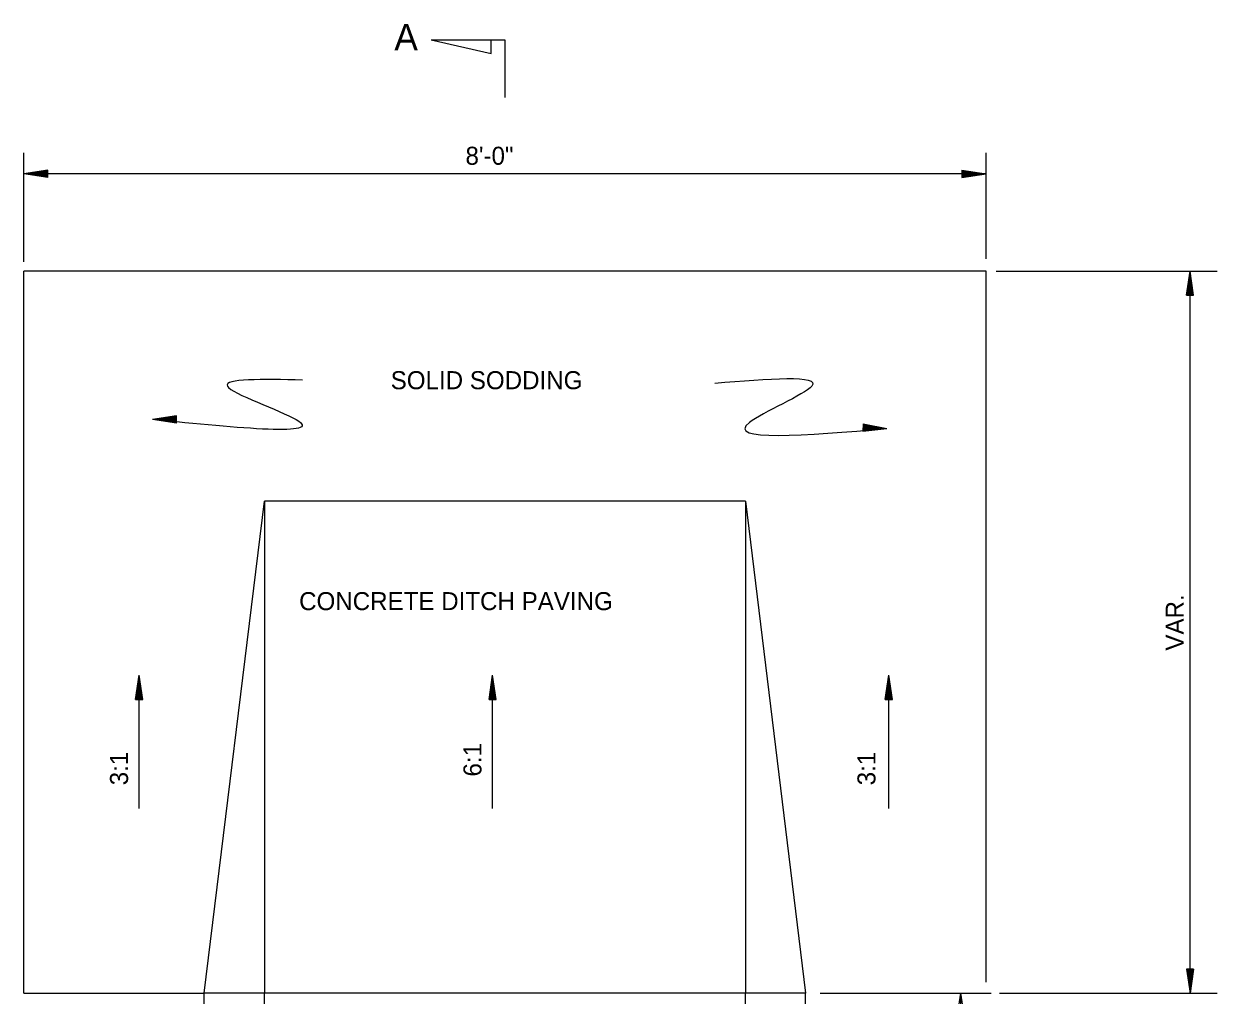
# Model space of a CAD drawing. Extents: x 635488 to 635865, y 290537 to 290973.
# Drawn here: x 635632.8 to 635672.47, y 290826.85 to 290859.13 of the extents above; entities that cross this region are included whole.
import ezdxf

# ---------------------------------------------------------------- set-up
doc = ezdxf.new("R2010")
doc.units = 0
doc.layers.add('Default', color=7, linetype='Continuous')
doc.layers.add('R_Dimension', color=7, linetype='Continuous')

msp = doc.modelspace()

# ---------------------------------------------------------------- linework, layer by layer
at = {"layer": 'Default'}
for p, q in [((635632.798, 290851.226), (635632.798, 290854.85)), ((635664.79, 290851.326), (635664.79, 290854.85)), ((635664.79, 290850.914), (635632.798, 290850.914)), ((635632.798, 290826.914), (635632.798, 290850.914)), ((635664.79, 290827.282), (635664.79, 290850.914)), ((635665.13, 290850.914), (635672.474, 290850.914)), ((635638.798, 290826.914), (635640.794, 290843.274)), ((635656.794, 290843.274), (635640.794, 290843.274)), ((635640.794, 290843.274), (635640.794, 290826.914)), ((635656.794, 290843.274), (635656.794, 290826.914)), ((635656.794, 290843.274), (635658.79, 290826.914)), ((635632.798, 290826.914), (635638.798, 290826.914)), ((635638.798, 290788.918), (635638.798, 290826.914)), ((635658.79, 290826.914), (635638.798, 290826.914)), ((635640.794, 290794.914), (635640.794, 290826.914)), ((635656.79, 290794.914), (635656.79, 290826.914)), ((635658.79, 290788.918), (635658.79, 290826.914)), ((635659.274, 290826.918), (635664.962, 290826.918)), ((635665.234, 290826.918), (635672.474, 290826.918))]:
    msp.add_line(p, q, dxfattribs=at)
at = {"layer": 'R_Dimension'}
for p, q in [((635646.338, 290858.602), (635648.794, 290858.602)), ((635646.338, 290858.602), (635648.338, 290858.15)), ((635648.338, 290858.15), (635648.338, 290858.602)), ((635648.794, 290858.602), (635648.794, 290856.69)), ((635648.794, 290858.602), (635648.794, 290857.15)), ((635633.598, 290854.266), (635632.798, 290854.146)), ((635664.79, 290854.146), (635632.798, 290854.146)), ((635633.598, 290854.026), (635632.798, 290854.146)), ((635633.598, 290854.246), (635632.93, 290854.146)), ((635633.598, 290854.046), (635632.93, 290854.146)), ((635633.598, 290854.226), (635633.07, 290854.146)), ((635633.598, 290854.066), (635633.07, 290854.146)), ((635633.598, 290854.206), (635633.202, 290854.146)), ((635633.598, 290854.086), (635633.202, 290854.146)), ((635633.598, 290854.186), (635633.338, 290854.146)), ((635633.598, 290854.106), (635633.338, 290854.146)), ((635633.598, 290854.166), (635633.47, 290854.146)), ((635633.598, 290854.126), (635633.47, 290854.146)), ((635633.598, 290854.026), (635633.598, 290854.266)), ((635663.99, 290854.266), (635664.79, 290854.146)), ((635663.99, 290854.266), (635663.99, 290854.026)), ((635663.99, 290854.246), (635664.658, 290854.146)), ((635663.99, 290854.226), (635664.518, 290854.146)), ((635663.99, 290854.206), (635664.386, 290854.146)), ((635663.99, 290854.186), (635664.25, 290854.146)), ((635663.99, 290854.166), (635664.118, 290854.146)), ((635663.99, 290854.026), (635664.79, 290854.146)), ((635663.99, 290854.106), (635664.25, 290854.146)), ((635663.99, 290854.066), (635664.518, 290854.146)), ((635663.99, 290854.046), (635664.658, 290854.146)), ((635663.99, 290854.086), (635664.386, 290854.146)), ((635663.99, 290854.126), (635664.118, 290854.146)), ((635671.454, 290850.114), (635671.574, 290850.914)), ((635671.574, 290826.918), (635671.574, 290850.914)), ((635671.694, 290850.114), (635671.574, 290850.914)), ((635671.474, 290850.114), (635671.574, 290850.782)), ((635671.494, 290850.114), (635671.574, 290850.642)), ((635671.514, 290850.114), (635671.574, 290850.51)), ((635671.674, 290850.114), (635671.574, 290850.782)), ((635671.654, 290850.114), (635671.574, 290850.642)), ((635671.634, 290850.114), (635671.574, 290850.51)), ((635671.454, 290850.114), (635671.694, 290850.114)), ((635671.534, 290850.114), (635671.574, 290850.374)), ((635671.554, 290850.114), (635671.574, 290850.242)), ((635671.614, 290850.114), (635671.574, 290850.374)), ((635671.594, 290850.114), (635671.574, 290850.242)), ((635637.874, 290846.102), (635637.074, 290845.982)), ((635637.874, 290845.862), (635637.074, 290845.982)), ((635637.874, 290846.082), (635637.206, 290845.982)), ((635637.874, 290845.882), (635637.206, 290845.982)), ((635637.874, 290846.062), (635637.346, 290845.982)), ((635637.874, 290845.902), (635637.346, 290845.982)), ((635637.874, 290846.042), (635637.478, 290845.982)), ((635637.874, 290845.922), (635637.478, 290845.982)), ((635637.874, 290846.022), (635637.614, 290845.982)), ((635637.874, 290845.942), (635637.614, 290845.982)), ((635637.874, 290846.002), (635637.746, 290845.982)), ((635637.874, 290845.962), (635637.746, 290845.982)), ((635637.874, 290845.862), (635637.874, 290846.102)), ((635660.702, 290845.838), (635660.69, 290845.598)), ((635660.694, 290845.734), (635660.822, 290845.71)), ((635660.698, 290845.818), (635661.362, 290845.686)), ((635660.698, 290845.798), (635661.222, 290845.694)), ((635660.698, 290845.778), (635661.09, 290845.698)), ((635660.698, 290845.754), (635660.954, 290845.706)), ((635660.702, 290845.838), (635661.494, 290845.682)), ((635660.69, 290845.638), (635661.222, 290845.694)), ((635660.69, 290845.618), (635661.362, 290845.686)), ((635660.69, 290845.598), (635661.494, 290845.682)), ((635660.694, 290845.698), (635660.822, 290845.71)), ((635660.694, 290845.678), (635660.954, 290845.706)), ((635660.694, 290845.658), (635661.09, 290845.698)), ((635636.514, 290836.682), (635636.634, 290837.482)), ((635636.634, 290833.054), (635636.634, 290837.482)), ((635636.754, 290836.682), (635636.634, 290837.482)), ((635648.266, 290836.682), (635648.386, 290837.482)), ((635648.386, 290833.054), (635648.386, 290837.482)), ((635648.506, 290836.682), (635648.386, 290837.482)), ((635661.442, 290836.682), (635661.562, 290837.482)), ((635661.562, 290833.054), (635661.562, 290837.482)), ((635661.682, 290836.682), (635661.562, 290837.482)), ((635636.534, 290836.682), (635636.634, 290837.35)), ((635636.554, 290836.682), (635636.634, 290837.21)), ((635636.574, 290836.682), (635636.634, 290837.078)), ((635636.734, 290836.682), (635636.634, 290837.35)), ((635636.714, 290836.682), (635636.634, 290837.21)), ((635636.694, 290836.682), (635636.634, 290837.078)), ((635648.286, 290836.682), (635648.386, 290837.35)), ((635648.306, 290836.682), (635648.386, 290837.21)), ((635648.326, 290836.682), (635648.386, 290837.078)), ((635648.486, 290836.682), (635648.386, 290837.35)), ((635648.466, 290836.682), (635648.386, 290837.21)), ((635648.446, 290836.682), (635648.386, 290837.078)), ((635661.462, 290836.682), (635661.562, 290837.35)), ((635661.482, 290836.682), (635661.562, 290837.21)), ((635661.502, 290836.682), (635661.562, 290837.078)), ((635661.662, 290836.682), (635661.562, 290837.35)), ((635661.642, 290836.682), (635661.562, 290837.21)), ((635661.622, 290836.682), (635661.562, 290837.078)), ((635636.514, 290836.682), (635636.754, 290836.682)), ((635636.594, 290836.682), (635636.634, 290836.942)), ((635636.614, 290836.682), (635636.634, 290836.81)), ((635636.674, 290836.682), (635636.634, 290836.942)), ((635636.654, 290836.682), (635636.634, 290836.81)), ((635648.266, 290836.682), (635648.506, 290836.682)), ((635648.346, 290836.682), (635648.386, 290836.942)), ((635648.366, 290836.682), (635648.386, 290836.81)), ((635648.426, 290836.682), (635648.386, 290836.942)), ((635648.406, 290836.682), (635648.386, 290836.81)), ((635661.442, 290836.682), (635661.682, 290836.682)), ((635661.522, 290836.682), (635661.562, 290836.942)), ((635661.542, 290836.682), (635661.562, 290836.81)), ((635661.602, 290836.682), (635661.562, 290836.942)), ((635661.582, 290836.682), (635661.562, 290836.81)), ((635671.454, 290827.718), (635671.574, 290826.918)), ((635671.694, 290827.718), (635671.454, 290827.718)), ((635671.474, 290827.718), (635671.574, 290827.05)), ((635671.494, 290827.718), (635671.574, 290827.19)), ((635671.514, 290827.718), (635671.574, 290827.322)), ((635671.534, 290827.718), (635671.574, 290827.458)), ((635671.554, 290827.718), (635671.574, 290827.59)), ((635671.694, 290827.718), (635671.574, 290826.918)), ((635671.614, 290827.718), (635671.574, 290827.458)), ((635671.654, 290827.718), (635671.574, 290827.19)), ((635671.674, 290827.718), (635671.574, 290827.05)), ((635671.634, 290827.718), (635671.574, 290827.322)), ((635671.594, 290827.718), (635671.574, 290827.59)), ((635663.83, 290826.118), (635663.95, 290826.918)), ((635663.95, 290818.918), (635663.95, 290826.918)), ((635664.07, 290826.118), (635663.95, 290826.918))]:
    msp.add_line(p, q, dxfattribs=at)
for points in [[(635642.062, 290847.294), (635639.566, 290847.094), (635641.854, 290845.982), (635637.074, 290845.982)], [(635655.778, 290847.194), (635658.998, 290847.094), (635656.922, 290845.882), (635661.494, 290845.682)]]:
    msp.add_spline(points, degree=3, dxfattribs=at)

# ---------------------------------------------------------------- texts
at = {"layer": 'Default'}
msp.add_text('CONCRETE DITCH PAVING', height=0.6, dxfattribs=at).set_placement((635641.95, 290839.646))
at = {"layer": 'R_Dimension'}
for s, height, p in [('A', 0.875, (635645.118, 290858.258)), ('8\'-0"', 0.6, (635647.482, 290854.45)), ('SOLID SODDING', 0.6, (635644.995, 290846.99))]:
    msp.add_text(s, height=height, dxfattribs=at).set_placement(p)
for s, p in [('VAR.', (635671.366, 290838.3)), ('6:1', (635648.014, 290834.116)), ('3:1', (635636.262, 290833.825)), ('3:1', (635661.114, 290833.825))]:
    msp.add_text(s, height=0.6, rotation=90, dxfattribs=at).set_placement(p)

doc.saveas('drawing.dxf')
